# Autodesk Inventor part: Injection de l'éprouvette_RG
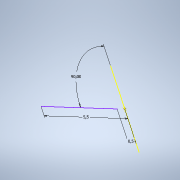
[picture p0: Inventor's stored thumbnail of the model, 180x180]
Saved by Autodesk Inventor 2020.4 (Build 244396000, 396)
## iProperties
Created: 2021-10
Part Number: Injection de l'éprouvette_RG
Material: Générique
Document SubType Name: Modeling
Designer: mel
Density: 1 g/cm^3
Appearance: Par défaut
Author: mel
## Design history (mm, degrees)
node "Emplacement du point d'injection 1_PZ:1"
node "Plan de construction1"
sketch "Esquisse1"
  geometry: L1 (-25.574, -3.193)-(-29.194, -4.896) reference; L2 (-27.597, -3.592)-(-28.874, -0.878); 1 further point
  constraints: 2 end point
  dimensions: "d0" = 0 dimension on point (-27.384, -4.045) L1.start L1.end L1 L2.end L2 L2.start; "d1" = 3.5 distance of point (-27.384, -4.045) L2.end; "d2" = 90 deg angle of L2 L1; "d4" = 0.5 distance of L2.start point (-27.384, -4.045)
  node "Référence1"
other parameters: "d0" = 0
